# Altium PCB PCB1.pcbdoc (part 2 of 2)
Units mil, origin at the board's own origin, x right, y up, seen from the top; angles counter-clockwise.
Board outline 4437 x 2665.4 mil, 2 copper layers (Top Layer, Bottom Layer), stack 62.206 mil thick; 104 components, 74 nets, 471 pads, 378 vias.
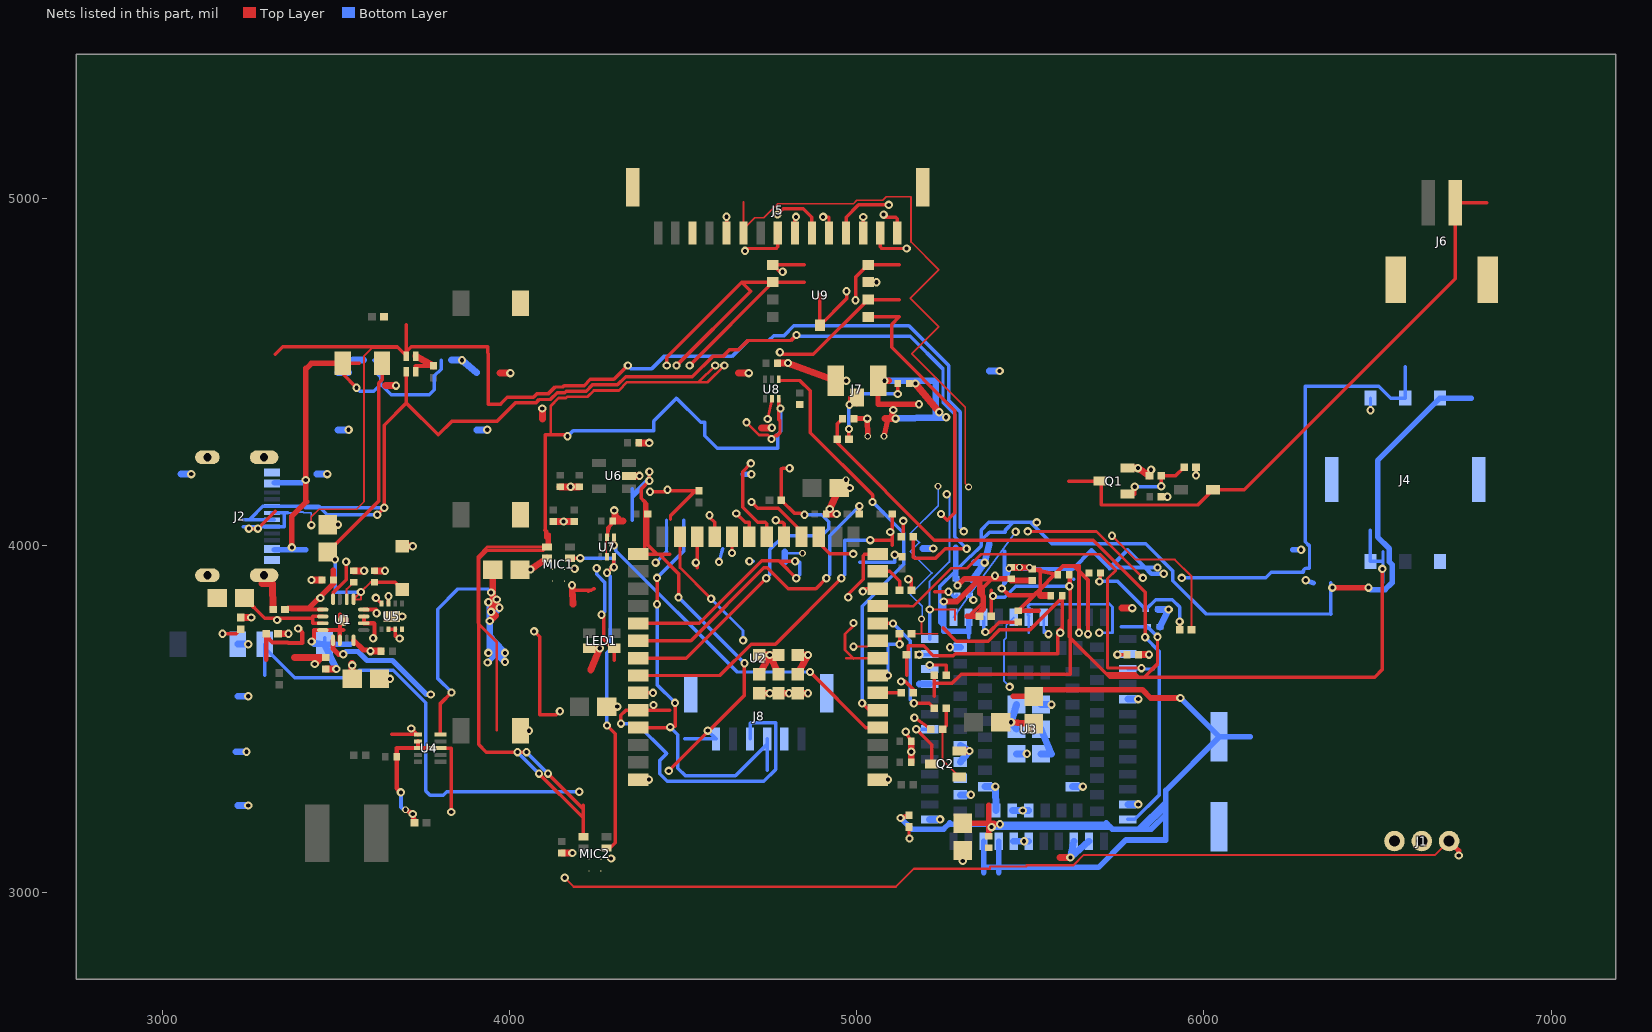
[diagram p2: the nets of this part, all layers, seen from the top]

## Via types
v1: diameter 24, hole 12, Top Layer to Bottom Layer, 334 vias
v2: diameter 24.02, hole 12, Top Layer to Bottom Layer, 30 vias
v3: diameter 19.8, hole 11.8, Top Layer to Bottom Layer, 8 vias
v4: diameter 19.7, hole 11.8, Top Layer to Bottom Layer, 3 vias
v5: diameter 20, hole 12, Top Layer to Bottom Layer, 3 vias

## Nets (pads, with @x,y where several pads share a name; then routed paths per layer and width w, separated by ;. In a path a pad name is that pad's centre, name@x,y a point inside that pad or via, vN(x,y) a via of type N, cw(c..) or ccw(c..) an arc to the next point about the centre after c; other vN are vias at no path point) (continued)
GND: C1.2 C2.2 C3.2 C4.2 C5.2 C6.2 C7.2 C8.2 C9.2 C10.2 C11.2 C12.2 C13.2 C14.2 C15.2 C16.2 C17.2 C18.2 C19.2 C20.2 C21.2 C22.2 C23.2 C24.2 C25.2 C26.2 C27.2 C28.2 C29.2 C30.2 C31.2 C32.2 C33.2 C34.2 C35.2 C36.2 C37.2 C38.2 C39.2 D1.2 D2.2 D3.2 D4.2 D5.2 D6.2 D8.2 J1.2 J2.1 J2.2 J2.3 J2.4 J2.A1B12 J2.B1A12 J4.8 J4.C5 J5.3 J5.16 J5.17 J6.3 J6.4 J7.1 J7.3 J8.2 J8.7 J8.8 LED1.2 MIC1.2 MIC1.3 MIC2.3 Q1.2 Q2.2 R1.2 R2.2 R4.2 R7.2 R8.2 R20.2 R25.2 R27.2 SW1.2 SW2.2 SW3.2 SW4.2 SW5.2 U1.4 U1.6 U1.8 U1.17 U2.1 U2.40 U2.41 U3.1 U3.10 U3.27 U3.34 U3.36 U3.37 U3.40 U3.41 U3.45 U3.46 U3.47 U3.48 U3.70 U3.71 U3.72 U3.73 U3.88 U3.89 U3.90 U3.91 U3.92 U3.93 U3.94 U3.95 U3.100 U4.2 U4.3 U4.8 U5.4 U5.9 U6.2 U7.2 U7.5 U8.2 U9.4 | length 9680.9
  Top Layer w5: U7.2@4278,3966.6 U7.5@4278,4023.4
  Top Layer w8: U7.5@4279.99,4023.45 4280.22,4024.22 4282,4030.86 4289.01,4057.01 v1(4300.71,4100.67) ; v1(4742.73,4363.89) U8.2@4754.99,4421.56
  Top Layer w10: U4.8@3792.11,3415.5 3831.19,3415.5 v1(3831.19,3231.61) ; v1(4179.06,3884.58) 4179.06,3870.89 4179.67,3870.89 4234.33,3870.89 ; 4226.19,3867.09 4234.33,3870.89 ; 4242.5,3874.7 4234.33,3870.89 ; U7.5@4280,4024 4280.22,4024.22 4282,4026 4282,4030.86 4282,4050 4289.01,4057.01 C29.2@4298,4066 ; C29.2@4296.54,4070 4306.03,4075.5 4315.55,4081 ; 4316,4066 4326.5,4070 ; C12.2@4911.54,4090 v1(4921.82,4104.74) ; v1(5140.5,3462.71) C10.2@5156.54,3435 ; C39.2@5150.54,4466 v1(5168.5,4466) ; v1(5165.49,3503.27) R27.2@5212.96,3470 ; C17.2@5505,3931.54 5528.5,3931.5 5528.5,3926.22 5528.5,3874.5 5528.5,3855 ; R25.2@5842.96,4200 v1(5847.66,4217.39) ; C31.2@5876.54,4140 v1(5894.5,4140)
  Top Layer w12: v1(3428.83,3722.9) 3436,3732 3436,3756 3510,3756 3510,3755.5 ; U1.4@3460.95,3755.47 3510,3755.5 ; U1.6@3510,3726 3510,3755.5 ; U1.6@3510.16,3725.95 3510.2,3755.5 ; 3510.2,3800.9 3510.2,3755.5 ; 3520,3755.5 3510.2,3755.5 ; 3674,3300 v1(3686,3288) ; 3674,3300.5 C18.2@3674.04,3390.5 3674,3415.5 U4.3@3735.02,3415.5 ; D2.2@3728.78,4500 3728.8,4517 R7.2@3780,4517.04 ; U4.2@3735.02,3435.18 U4.3@3735.02,3415.5 ; U4.8@3792.11,3415.5 U4.3@3735.02,3415.5 ; v1@5418,3876 5438,3856 5510,3856 ; C16.2@5445,3936.54 C17.2@5505,3931.54 5528.5,3926.22 C14.2@5570.74,3916.74 ; C37.2@5465,3811.54 5525,3811.5 ; C37.2@5466,3812 5510,3856 ; C14.2@5578.46,3915 C14.2@5570.74,3916.74 ; v1(5640,3748) 5640,3926 ; v1(5666,3744) 5666,3900 5640,3926 ; 3510,3755.5 3510.2,3755.5 ; 5510,3856 5528.5,3874.5 C14.2@5570.74,3916.74 ; C14.2@5570.74,3916.74 5594,3940 5626,3940 ; 5626,3940 5640,3940 5640,3926 ; 5626,3940 5640,3926
  Top Layer w15: U1.8@3550,3726 3578,3698 3588,3698 v1(3598.5,3695) ; v3(3699.3,3237.93) v1(3720.09,3225.93) R20.2@3725.46,3200.5 ; SW1.2@4030.9,3465.35 v1(4054.9,3465.4) ; C12.2@4911.54,4090 4928.74,4119.86 4954.8,4165 v3(4968.5,4188.73) ; C12.2@4912,4090 4918,4096 v1(4921.82,4104.74) ; C38.2@4991.54,4365 v1(5029.5,4365) v3(5031.28,4314.03) ; U9.4@5032.38,4758.03 v1(5056.4,4758) ; J7.3@5061.02,4474.1 5061,4406.1 v1(5178.78,4406.1) ; v3(5078.19,4314.14) 5089,4365 ; 5096.5,4365 v1(5104.53,4389.73) ; v3(5468.36,3936.65) 5469.42,3936.5 C17.2@5505,3931.54 ; v3@5475,3936.5 v3(5497,3936.5)
  Top Layer w20: R2.2@3225,3792.04 v1(3255,3792) ; 3285.6,3890 3315.6,3890 R4.2@3317.96,3815 ; R1.2@3332.04,3745 v1(3362,3745) ; v1(3428.5,3900) C7.2@3458.46,3900 ; C5.2@3470,3643.46 v1(3500,3643.5) ; C3.2@3475,4059.37 v1(3505,4059.4) ; C6.2@3550,3926.54 v1(3580,3926.5) ; v1(3598.5,3695) C21.2@3628.46,3695 ; C2.2@3610,3926.54 v1(3640,3926.5) ; C4.2@3624.37,3615 v1(3654.4,3615) ; 3642,4460 v1(3672,4460) ; U5.9@3660,3795 v1(3690,3795) ; D8.2@3690,3997.4 v1(3720,3997.4) ; D1.2@3728.78,4545 R7.2@3780,4517.04 ; 3971.5,4496 v1(4001.5,4496) ; C19.2@4029.37,3930 v1(4059.4,3930) MIC1.2@4107.01,3962.89 ; 4093.5,4364.1 v1(4093.5,4394.1) ; C23.2@4125,4068.46 v1(4155,4068.5) C25.2@4185,4068.46 ; C22.2@4145,4168.46 v1(4175,4168.5) C28.2@4200,4168.46 ; C26.2@4150,3113.46 v1(4180,3113.5) ; v1(4179.06,3884.58) 4179.67,3870.89 4181.5,3830 ; LED1.2@4228.98,3703.34 v1(4259,3703.3) 4233,3640 ; C20.2@4279.37,3535 v1(4309.4,3535) ; C29.2@4296.54,4070 4326.5,4070 ; v1(4300.71,4100.67) C29.2@4306.03,4075.5 ; U6.2@4343.31,4199.99 v1(4373.3,4200) ; U2.40@4370.51,3324.8 v1(4400.5,3324.8) ; C27.2@4371.54,4295 v1(4401.5,4295) ; 4658.5,4495.9 v1(4688.5,4495.9) ; U2.41@4718.94,3573.62 v1(4748.9,3573.6) ; U2.41@4718.94,3628.74 v1(4748.9,3683.9) ; U2.41@4718.94,3683.86 v1(4748.9,3683.9) ; 4725,4338.5 v1(4755,4338.5) ; C30.2@4771.54,4525 v1(4801.5,4525) J7.1@4938.98,4474.1 v1(4969,4474.1) ; U2.41@4774.06,3573.62 v1(4804.1,3573.6) ; U2.41@4774.06,3628.74 v1(4748.9,3683.9) ; U2.41@4774.06,3683.86 v1(4748.9,3683.9) ; U2.41@4829.18,3573.62 v1(4859.2,3573.6) ; U2.41@4829.18,3628.74 v1(4859.2,3683.9) U2.41@4829.18,3683.86 ; C12.2@4911.54,4090 4912,4090 v1(4941.5,4090) ; v1(4921.82,4104.74) 4928.74,4119.86 C11.2@4949.37,4165 4954.8,4165 v1(4979.4,4165) ; U2.1@5059.49,3324.8 v1(5089.5,3324.8) ; J7.3@5061.02,4474.1 5091,4474.1 ; 5081.5,4365 5089,4365 5096.5,4365 v1(5111.5,4365) ; C9.2@5156.54,3375 v1(5156.5,3405) C10.2@5156.54,3435 ; v1(5168.5,4466) v1(5237.42,4383.44) ; Q2.2@5294.37,3407.4 v1(5324.4,3407.4) ; v1(5305,3090.6) C33.2@5305,3120.63 ; C8.2@5414.37,3490 v1(5444.4,3490) C34.2@5510,3485.63 ; C16.2@5445,3936.54 5469.42,3936.5 v3@5475,3936.5 ; 5528.5,3855 C15.2@5558.46,3855 ; 5585,3100.3 v1(5615,3100.3) ; 5763.1,3818.8 v1(5793.1,3818.8) ; Q1.2@5779.37,4222.4 v1(5809.4,4222.4) R25.2@5842.96,4200 ; C36.2@5811.54,3685 v1(5841.5,3685)
  Inner2 w12: v1(5640,3748) 5666,3722 5688,3722 ; v1(5666,3744) 5688,3722 ; v1(5866,3936) 5866,3880 ; v1(5884,3918) 5884,3898 5866,3880 ; 5688,3722 5708,3722 ; 5688,3722 5698,3712 5708,3722 ; 5708,3722 5866,3880
  Bottom Layer w5: U3.95@5278.46,3792.84 5324.22,3855.73 v1(5457.19,4038.74)
  Bottom Layer w6: 4792,3977.11 v3(4842.86,3977.11)
  Bottom Layer w10: SW4.2@3466.02,3715 SW4.2@3466,3733 ; v1(4602.55,3952.06) 4612.9,3990.7 ; 5227.1,4368.7 v1(5237.42,4383.44) ; D5.2@5324,3856 5324.22,3855.73 v1(5335.57,3842.21) ; v1(5417.39,3875.39) 5425,3891.7
  Bottom Layer w12: v1(3686,3288) 3686,3246 3692,3240 v3(3699.3,3237.93) ; 5425,3891.7 5425,3981.7 ; v3@5430,3932 5438.09,3932 5622,3932 5676,3986 5726,3936 ; v1(5866,3936) 5830,3936 ; v1(5884,3918) 5848,3918 5830,3936 ; 5726,3936 5730,3936 ; 5726,3936 5728,3934 5730,3936 ; 5730,3936 5780,3986 5830,3936 ; 5730,3936 5830,3936
  Bottom Layer w15: SW4.2@3466,3714 3436,3714 v1(3428.83,3722.9) SW4.2@3466.02,3715 3541,3715 ; 4671.8,4204.6 v1(4695.8,4204.6) ; 5425,3891.7 5438.09,3932 v3(5438.29,3932.59) ; 6255.9,3987.1 v1(6279.9,3987.1) ; v1(6292.98,3899.12) 6315.8,3891.7
  Bottom Layer w20: 3051.9,4205 v1(3081.9,4205) ; 3211,3405 v1(3241,3405) ; 3216,3250 v1(3246,3250) ; 3216,3565 v1(3246,3565) ; SW5.2@3216.02,3715 v1(3246,3715) ; 3443.6,4205 v1(3473.6,4205) ; SW4.2@3466.02,3715 v1(3500,3643.5) ; 3505.4,4332.7 v1(3535.4,4332.7) ; 3505.4,4497.3 3535.4,4497.3 ; 3548,4533.3 3578,4533.3 ; 3832,4533.3 v1(3862,4533.3) 3904.6,4497.3 ; 3904.6,4332.7 v1(3934.6,4332.7) ; 4792,3951.3 4792,3977.11 4792,3981.3 ; v1(5079,4474.1) 5227.1,4474.1 5227.1,4368.7 ; v1(5111.5,4365) 5227.1,4368.7 ; 5179.6,3599.9 U3.10@5209.57,3599.91 ; 5189.7,3990.7 v1(5219.7,3990.7) ; U3.1@5209.57,3210.16 v1(5239.6,3210.2) ; v1(5257.1,4368.7) 5227.1,4368.7 ; v1(5268.2,3706.2) U3.100@5298.15,3706.22 ; U3.45@5298.15,3281.01 v1(5328.2,3281) ; U3.47@5298.15,3375.51 v1(5324.4,3407.4) U3.48@5298.15,3422.76 ; 5333,3900 v1(5368,3950) ; 5338,3950 v1(5368,3950) ; U3.73@5369.02,3304.64 v1(5399,3304.6) U3.72@5400.51,3235.74 ; 5381.2,4003.1 v1(5368,3950) ; 5381.2,4502.3 v1(5411.2,4502.3) ; U3.71@5447.76,3235.74 v1(5477.8,3235.7) U3.70@5495,3235.74 ; U3.41@5451.69,3147.16 v1(5481.7,3147.2) U3.40@5495,3147.16 ; U3.89@5459.57,3399.12 v1(5489.6,3399.1) ; U3.90@5459.57,3469.99 v1(5444.4,3490) U3.91@5459.57,3540.86 ; U3.94@5530.43,3399.12 5560.4,3399.1 U3.93@5530.43,3469.99 ; U3.92@5530.43,3540.86 v1(5560.4,3540.9) ; U3.88@5620.98,3304.64 v1(5651,3304.6) ; U3.37@5624.92,3147.16 v1(5615,3100.3) U3.36@5668.23,3147.16 ; U3.34@5780.43,3253.45 v1(5810.4,3253.5) ; U3.27@5780.43,3556.61 v1(5810.4,3556.6) ; D3.2@5868,3815 v1(5898,3815) D4.2@5873,3765
  other v1: 4291.7,3097.5 4186.7,3932.5
GPIO0_BOOT: J8.6 R6.1 SW4.1 U2.27 | length 3392.4
  Top Layer w10: U2.27@4370.51,3974.8 4423.2,3974.8 ; U2.27@4388,3978 4388,4126 ; R6.1@4394,4094 4394,4120 4388,4126 ; 4397,4000 R6.1@4397.04,4090 ; 4398,4000 4423.2,3974.8 ; v1(4402,4212) v1(4402,4186) 4378,4162 4378,4136 4388,4126 ; 4424,3974 4423.2,3974.8 ; 4430,3974 4486,3918 v1(4486,3850) ; v1(4458,3350) 4676,3568 v1(4676,3660) ; 4460.5,3974.8 4423.2,3974.8
  Top Layer w15: U2.27@4370.51,3974.8 U2.27@4388,3978
  Inner2 w10: v1(4200,3290) 4260,3350 v1(4458,3350)
  Bottom Layer w10: 3294,3625 SW4.1@3293.98,3715 ; SW4.1@3298,3700 3380,3618 3544,3618 3566,3640 3664,3640 3758,3546 3758,3292 3770,3280 3808,3280 3818,3290 v1(4200,3290) ; 4352,4072 4352,4136 ; 4352,4162.8 4352,4144 ; 4352.9,4072 4352.9,4072.8 4352.9,4136.9 ; v1(4402,4186) 4352.9,4136.9 ; v1(4402,4212) 4402,4194 4352,4144 ; v1(4486,3850) v1(4676,3660) ; 4503.9,3441.9 J8.6@4593.9,3441.93 ; v1(4570,3466) J8.6@4594,3442 ; 4352,4136 4352.9,4136.9 ; 4352,4136 4352,4144
I2C_SCL: J5.13 U2.17 U5.7 | length 2688.9
  Top Layer w9.88: U5.7@3650.16,3831.91 v2(3650.16,3853.23)
  Top Layer w10: U2.17@4890,4025.2 4890,4007.07 4921.75,3975.32 v2(4989.2,3975.32) ; J5.13@5017.97,4900.05 v2(5017.97,4945.71)
  Inner1 w9.88: v2(3650.16,3853.23) 3786.05,3989.12 4213.43,3989.12 4240.12,3962.43 4295.42,3962.43 4335.48,4002.49 4962.03,4002.49 v2(4989.2,3975.32)
  Inner1 w10: v2(4989.2,3975.32) 5040.83,3975.32 5071.8,4006.29 5071.8,4170.93 5054.78,4187.95 5054.78,4448.82 5020.34,4483.26 5020.34,4943.34 v2(5017.97,4945.71)
I2C_SDA: J5.12 U2.12 U5.8 | length 3002.8
  Top Layer w9.88: v2(3613.83,3848.55) U5.8@3630.47,3831.91 ; J5.12@4968.76,4900.07 4968.77,4944.97 5004.56,4980.77 v2(5091.58,4980.77)
  Top Layer w10: v2(5017.11,3867.24) 5018.45,3868.58 5018.45,3870.23 5023.03,3874.81 U2.12@5059.49,3874.8
  Inner1 w9.88: v2(3613.83,3848.55) 3644.29,3818.09 3848.42,3818.09 3908.93,3757.58 3950.59,3757.58 3969.47,3776.46 4078.2,3776.46 4083.65,3771.01 4816.79,3771.01 4858.95,3813.17 4973.06,3813.17 5017.11,3857.23 v2(5017.11,3867.24) 5042.72,3867.24 5159.99,3984.51 5159.99,4192.16 5205.21,4237.38 5205.21,4867.14 v2(5091.58,4980.77)
LCD_BL_PWM: J5.11 U2.21 | length 1243.8
  Top Layer w6: J5.11@4919.6,4900 J5.11@4919.55,4900.07
  Top Layer w10: v2(4652.35,4091.62) 4677.75,4066.22 4690,4066.22 U2.21@4690,4025.2 ; v2(4902.64,4946.21) 4903.82,4945.03 4919.56,4945.03 J5.11@4919.55,4900.07
  Inner1 w10: v2(4652.35,4091.62) 4643.45,4100.52 4643.45,4857.79 4763.88,4978.22 4870.63,4978.22 v2(4902.64,4946.21)
LCD_CS: J5.8 U2.18 | length 1081.3
  Top Layer w10: v2(4677.56,4848.19) 4684.48,4855.11 4767.34,4855.11 4771.92,4859.69 J5.8@4771.91,4900.07 ; v2(4696.31,4124.56) 4713.81,4107.06 4773.63,4107.06 4840,4040.69 U2.18@4840,4025.2
  Inner1 w10: v2(4677.56,4848.19) 4657.64,4828.27 4657.64,4163.23 v2(4696.31,4124.56)
LCD_DC: J5.9 U2.19 | length 1138.6
  Top Layer w10: v2(4766.17,4072.05) 4772,4066.22 4785.42,4066.22 4790,4061.64 U2.19@4790,4025.2 ; J5.9@4821.12,4900.07 4821.13,4942.98 v2(4824.46,4946.3)
  Inner1 w10: v2(4766.17,4072.05) 4833.37,4139.25 4908.46,4139.25 4925.94,4156.73 4925.94,4844.82 v2(4824.46,4946.3)
LCD_MOSI: J5.5 R22.2 | length 2142.7
  Top Layer w10: J5.5@4624.3,4900 J5.5@4624.27,4900.07 ; J5.5@4624.27,4900.07 v2(4624.28,4946.37) ; v2(5127.22,3607.57) 5139.42,3607.57 5162.04,3584.95 R22.2@5162.04,3575
  Inner1 w10: v2(4624.28,4946.37) 4685.34,5007.42 5097.79,5007.42 5285.71,4819.51 5285.71,4067.59 5255.77,4037.65 5255.77,3893.91 5146.15,3784.29 5146.15,3626.5 v2(5127.22,3607.57)
LCD_MOSI_MCU: R22.1 U2.6 | length 68.6
  Top Layer w10: U2.6@5059.49,3574.8 5059.7,3575 R22.1@5127.96,3575
LCD_RST: J5.10 U2.20 | length 1276.1
  Top Layer w10: v2(4694.37,4235.91) 4670.54,4212.08 4670.54,4109.88 4714.2,4066.22 4735.42,4066.22 4740,4061.64 U2.20@4740,4025.2 ; v2(4771.25,4952.84) 4788.24,4969.82 4845.54,4969.82 4870.34,4945.03 J5.10@4870.33,4900.07
  Inner1 w10: v2(4694.37,4235.91) 4719.39,4235.91 4879.34,4395.86 4879.34,4844.75 v2(4771.25,4952.84)
LCD_SCLK: J5.6 R23.2 | length 2364.6
  Top Layer w5: J5.6@4673.5,4900 J5.6@4673.48,4900.07 4673.5,4990.1 ; J5.6@4674,4912 4706,4944 4732,4944 4772,4984 4990,4984 5000,4994 5074,4994 5084,5004 5156,5004 5156,4874 5236,4794 5154,4712 5236,4630 5158,4552 5312,4398 5312,4178 v5(5322,4168) ; R23.2@5157.04,3745 5232,3745 ; 5186,3746 v5(5186,3788)
  Inner2 w5: v5(5234,4170) 5268,4170 5280,4158 5312,4158 v5(5322,4168)
  Bottom Layer w5: v5(5186,3788) 5188,3790 5188,3824 5154,3858 5216,3920 5154,3982 5180,4008 5154,4034 5234,4114 v5(5234,4170)
LCD_SCLK_MCU: R23.1 U2.7 | length 183.7
  Top Layer w10: U2.7@5059.49,3624.8 v1(5089.5,3624.8) ; v1(5123,3715) R23.1@5122.96,3745
  Bottom Layer w10: v1(5089.5,3624.8) 5089.5,3715 v1(5123,3715)
LED_DATA: LED1.3 U2.24 | length 703.7
  Top Layer w10: v1(4264,3800) 4270,3794 4270,3728 4294,3704 LED1.3@4302,3704 ; 4301,3668.3 LED1.3@4301.02,3703.34 ; 4540,3935.2 U2.24@4540,4025.2
  Inner2 w10: v1(4250,3934) 4292,3976 4510,3976 v1(4536,3950)
  Bottom Layer w10: v1(4250,3934) 4250,3916 4274,3892 4274,3810 v1(4264,3800)
LTE_ANT: C38.1 R29.1 U3.35 | length 1862.4
  Top Layer w10: R29.1@4942.96,4305 4942.96,4295 5222.96,4015 5680.43,4015 5830.43,3865 v1(5830.43,3735) ; R29.1@4942.96,4305 4943,4349.5 C38.1@4958.46,4365
  Bottom Layer w10: U3.35@5780.43,3210.16 5800.43,3210.15 5870.43,3280.15 5870.43,3695 v1(5830.43,3735)
LTE_ANT_CONN: C39.1 J7.2 R29.2 | length 346.8
  Top Layer w10: R29.2@4977.04,4305 v1(4977,4335) ; v1(4978.79,4404.69) 4978.79,4425.9 J7.2@5000,4425.9 J7.2@5000,4404.69 ; v1(5117.5,4436) C39.1@5117.46,4466
  Bottom Layer w10: v1(4977,4335) 4977,4404.69 v1(4978.79,4404.69) 5010.09,4436 v1(5117.5,4436)
MIC_CLK_1V8: MIC1.4 MIC2.4 U7.3 | length 1064.8
  Top Layer w6: v1(4299.7,3936.6) U7.3@4299.69,3966.55
  Top Layer w9.92: MIC2.4@4277.99,3127.89 4288.64,3127.89 4303.32,3142.57 4303.32,3457.24 v1(4279.69,3480.87) ; v1(4279.69,3920.87) 4299.69,3940.87 U7.3@4299.69,3966.55
  Top Layer w10: MIC1.4@4172.99,3962.89 v1(4203,3962.9)
  Bottom Layer w9.92: v1(4279.69,3480.87) 4279.69,3690.87 4289.69,3700.87 4289.69,3910.87 v1(4279.69,3920.87)
  Bottom Layer w10: v1(4203,3962.9) 4299.7,3962.9 v1(4299.7,3936.6)
MIC_DATA_1V8: MIC1.1 MIC2.1 U8.3 | length 4968.9
  Top Layer w8: 3962,3468 3962,3722 3910,3774 3908,3776 3908,3968 3936,3996 4106,3996 4107,3996 4114,3996 4114,4032 4112,4032 4107,4037 4105,4039 ; 4102,4044 4102,4042 4102,4022 4106,4018 ; 4118,4318 4118,4402 4140,4424 4162,4424 4166,4428 4224,4428 4242,4446 4314,4446 4338,4470 4544,4470 ; v1(4592,4518) 4544,4470 ; v1(4618,4518) 4570,4470 4544,4470 ; v1(4682,4354) 4718,4318 4744,4318 4748,4314 v1@4762,4314 ; v1(4754,4306) v1@4762,4314 ; 4778,4360 4778,4326 ; v1@4762,4314 4766,4318 4770,4318 4778,4326 ; v1@4762,4314 4770,4314 4778,4322 4778,4326
  Top Layer w10: v1(4048,3404) 3932,3404 3910,3426 3910,3774 3910,3962 3934,3986 4096,3986 MIC1.1@4106,3996 ; v1(4084,3342) 4208,3218 ; 4101,4043 4102,4042 4105,4039 ; 4102,4044 4102,4318 4118,4318 4162,4318 v1(4166,4314) ; MIC1.1@4107.01,3995.26 4107,3996 4107,4037 4107,4040.3 ; v1(4110,3342) 4212,3240 ; MIC2.1@4212.01,3160.26 4212,3240 ; 4212,3250.3 4212,3240 ; 4774.7,4361.6 U8.3@4774.69,4421.56 ; v1@4778,4394 v1(4780,4394)
  Inner2 w8: v1(4592,4518) 4682,4428 v1(4682,4354) ; v1(4618,4518) 4704,4432 4704,4356 v1(4754,4306)
  Bottom Layer w10: v1(4022,3404) v1(4084,3342) ; v1(4048,3404) v1(4110,3342) ; v1(4166,4314) 4182,4330 4414,4330 4414,4358 4480,4424 4550,4354 4562,4354 4562,4316 4598,4280 4772,4280 4772,4320 4780,4328 v1(4780,4394)
MIC_PDM_CLK: U2.4 U7.4 | length 1006.6
  Top Layer w9.92: v1(4299.69,4000.12) U7.4@4299.69,4023.45 ; v1(4865,3634.8) 5025,3474.8 U2.4@5059.49,3474.8
  Bottom Layer w9.92: v1(4299.69,4000.12) 4305.01,3994.8 4305.01,3984.8 4655,3634.8 v1(4865,3634.8)
MIC_PDM_DATA: U2.5 U8.4 | length 1218.6
  Top Layer w9.92: U8.4@4774.69,4478.44 4778.33,4474.8 4835,4474.8 4865,4444.8 4865,4324.8 5045,4144.8 v1(5045,4124.8) ; v1(5015,3544.8) 5035,3524.8 U2.5@5059.49,3524.8
  Bottom Layer w9.92: v1(5015,3544.8) 5015,3824.8 5135,3944.8 5135,4034.8 v1(5045,4124.8)
MICROSD_N5: R12.1 U9.7 | length 3420.9
  Top Layer w10: v1(4404,4154) v1@4452,4154 ; v1(4452,4518) 4452,4542 4668,4758 ; v1@4455,4157 R12.1@4545,4157.04 ; 4462.8,4074.84 4462.8,4084.84 4532.8,4154.84 4542.8,4154.84 R12.1@4545,4157.04 ; v1(4480,4518) 4694,4732 4668,4758 ; v1(4518,4518) U9.7@4758,4758 ; R12.1@4545,4157.04 R12.1@4545,4157.04 ; 4667.6,4758 4668,4758 ; 4847.6,4758 U9.7@4758,4758 ; 4668,4758 U9.7@4757.6,4758.03 U9.7@4758,4758
  Inner2 w10: v1(4404,4154) 4298,4154 4292,4160 ; v1(4452,4518) 4452,4474 ; v1(4454,4160) 4292,4160 ; v1(4480,4518) 4480,4502 4452,4474 ; v1(4518,4518) 4320,4320 4298,4320 ; v1(4690,3954) 4714,3930 4738,3954 4738,3984 4704,4018 4704,4060 4550,4060 4550,4126 4296,4126 4294,4124 4272,4124 4272,4160 ; 4272,4160 4260,4160 4260,4282 4272,4294 ; 4272,4160 4292,4160 ; 4272,4160 4272,4294 ; 4272,4294 4298,4320 ; 4298,4320 4452,4474
  Bottom Layer w10: v1(4690,3954) 4702,3954
MICROSD_N6: R13.1 U9.1 | length 1452.3
  Top Layer w10: U9.1@4893.15,4633.62 4893.2,4723.6 ; U9.1@4894,4634 4970,4710 v1(4970,4732) ; v1(5108.79,3972.51) 5130,3972.51 R13.1@5130,3967.04
  Inner2 w10: v1(4970,4732) 5066,4732 5142,4656 5142,4224 5268,4098 5268,4004 5230,3966 5118,3966 v1(5108.79,3972.51)
  Bottom Layer w10: 5008.6,3951.3 5108.79,3951.3 v1(5108.79,3972.51)
MODEM_DTR: U2.25 U3.19 | length 1368.4
  Top Layer w8: 4490,3935.2 4490,3936 ; U2.25@4490,4025.2 4490,3936 ; v1(4580,3846) 4490,3936
  Inner2 w8: v1(4672,3726) 4682,3736 5068,3736 5112,3692 5154,3692 5198,3736 5344,3736 5356,3724 5532,3724 v1(5552,3744)
  Bottom Layer w8: v1(4580,3846) 4672,3754 v1(4672,3726) ; 5538.3,3747.8 U3.19@5538.31,3792.84 ; 5542,3754 v1(5552,3744)
MODEM_PWRKEY_DRV: R26.1 U2.10 | length 364.5
  Top Layer w10: U2.10@5059.49,3774.8 v1(5104.02,3774.81) ; v1(5164.02,3544.81) 5208.15,3544.81 R26.1@5222.96,3530
  Bottom Layer w10: v1(5104.02,3774.81) 5154.02,3724.81 5154.02,3554.81 v1(5164.02,3544.81)
MODEM_PWRKEY_N: Q2.3 U3.7 | length 157.1
  Top Layer w10: v1(5170.94,3470) 5215.63,3425.31 Q2.3@5215.63,3370
  Bottom Layer w10: v1(5170.94,3470) U3.7@5209.57,3469.99
MODEM_RESET_N: C37.1 U3.15 | length 151.6
  Top Layer w10: v1(5370,3750) 5382,3750 5410,3778 ; 5410,3778.5 C37.1@5465,3778.46
  Bottom Layer w10: v1@5365.1,3747.8 U3.15@5365.08,3792.84
MODEM_RXD: U2.8 U3.18 | length 1897.7
  Top Layer w8: 4969.5,3674.8 4989.2,3674.8 ; 4990,3674 4989.2,3674.8 ; v1(4990,3776) 4990,3768 4966,3744 4966,3698 4989.2,3674.8 ; U2.8@5060,3674.8 U2.8@5059.49,3674.8 4989.2,3674.8 ; v1(5492,4040) 5690,4040 v1(5824,3906)
  Inner2 w8: v1(4990,3776) 5072,3776 5094,3798 5124,3798 5156,3766 5218,3766 v1(5492,4040) ; v1(5698,3748) 5698,3780 v1(5824,3906)
  Bottom Layer w8: 5495,3747.8 U3.18@5495,3792.84 ; U3.18@5496,3796 5492,3800 5498,3806 5492,3812 5498,3818 5492,3824 5498,3830 5720,3830 5724,3834 5736,3822 5736,3748 v1(5698,3748)
MODEM_STATUS: U2.11 U3.25 | length 1232.1
  Top Layer w8: U2.11@5059.49,3824.8 5149.5,3824.8 ; 5150,3824 5162,3824 5272,3934 5318,3934 5358,3974 5700,3974 5746,3928 5722,3904 5722,3646 v1(5820,3646)
  Bottom Layer w8: U3.25@5780.43,3643.22 5855.4,3643.2
MODEM_TXD: U2.9 U3.17 | length 790.2
  Top Layer w5: v1(4990,3708) 5030,3708 U2.9@5059.49,3724.8
  Inner2 w5: v1(4990,3708) 5038,3708 5114,3632 5400,3632 v1(5440,3592)
  Bottom Layer w5: v1(5440,3592) 5424,3608 5424,3728 5430,3734 5430,3770 U3.17@5452,3792
MODEM_VDD_EXT: C36.1 U3.24 | length 59.6
  Top Layer w9.84: v1(5750.4,3685) C36.1@5778.46,3685
  Bottom Layer w9.84: v1(5750.4,3685) 5780.4,3685 U3.24@5780.43,3686.53
MOTOR_GATE: Q1.1 R24.2 R25.1 | length 226.4
  Top Layer w10: Q1.1@5779.37,4147.6 5800.61,4147.6 v1(5800.61,4168.81) ; v1(5877,4170) R25.1@5877.04,4200 5918,4200 R24.2@5942.96,4225
  Bottom Layer w10: v1(5800.61,4168.81) 5877,4168.81 v1(5877,4170)
MOTOR_N: D7.2 J6.2 Q1.3 | length 1750.1
  Top Layer w10: 5610.6,4185 Q1.3@5700.63,4185 ; Q1.3@5704,4182 5704,4116 5982,4116 D7.2@6026,4160 ; D7.2@6026.16,4160 6116,4160 ; 6116.2,4160 6116,4160 ; J6.2@6724,4982 6724,4768 6116,4160 ; J6.2@6724.41,4986.95 6814.4,4986.9
MOTOR_PWM: R24.1 U2.35 | length 1960.6
  Top Layer w10: U2.35@4370.51,3574.8 v1(4412.59,3574.8) ; v1(5977.04,4201.37) R24.1@5977.04,4225
  Inner2 w10: v1(4412.59,3574.8) 4588.16,3750.37 5323.77,3750.37 5414.67,3841.27 5723.96,3841.27 5986.95,4104.26 5986.95,4191.46 v1(5977.04,4201.37)
POWER_CHARGE_N4: C7.1 J1.3 R4.1 U1.1 | length 4624.5
  Top Layer w6: v1(4158,3042) 4184,3016 5112,3016 5164,3068 5384,3068 5384,3074 5488,3074 5488,3078 5624,3078 5654,3108 6666,3108 J1.3@6706,3148
  Top Layer w10: 3492,3886 C7.1@3492,3890 ; v1(4070,3752) 4086,3736 4086,3512 4134,3512 v1(4144,3522) ; v1(6734,3106) 6734,3120
  Top Layer w12: 3370.9,3814.5 U1.1@3460.95,3814.53
  Top Layer w15: J1.3@6706.28,3147.69 6734,3120
  Top Layer w16: R4.1@3352.04,3815 3362,3818 3420,3818 3492,3890 C7.1@3492,3900 ; C7.1@3491.54,3900 3491.5,3928
  Inner2 w6: v1(4158,3042) 4158,3124
  Inner2 w10: v1(3454,3848) 3496,3848 3498,3850 3520,3850 3560,3890 4064,3890 4064,3758 v1(4070,3752) ; v1(4144,3522) 4152,3514 4152,3204 4118,3170 4160,3128 4180,3148 ; 6734,3072 v1(6734,3106)
POWER_CHARGE_N5: R1.1 U1.12 | length 518.5
  Top Layer w12: 3298,3670 R1.1@3298,3738 ; R1.1@3298,3746 R1.1@3297.96,3745 R1.1@3298,3738 ; v1(3390,3760) 3402,3748 3402,3718 3362,3718 3360,3720 3316,3720 R1.1@3298,3738 ; U1.12@3579.05,3814.53 v1@3614.1,3814.5 ; v1(3616,3804) v1@3616,3808
  Inner2 w12: v1(3390,3760) 3396,3766 3574,3766 3612,3804 v1(3616,3804)
POWER_CHARGE_N6: R2.1 U1.16 | length 624.4
  Top Layer w10: v2(3171.91,3745.07) 3212.11,3745.07 R2.1@3225,3757.96 ; U1.16@3490.47,3844.05 3490.48,3862.7 3528.15,3900.37 v2(3528.15,3952.37)
  Inner1 w10: v2(3171.91,3745.07) 3247.54,3820.7 3393.01,3820.7 3524.68,3952.37 v2(3528.15,3952.37)
POWER_CHARGE_N7: C6.1 U1.14 | length 57.8
  Top Layer w6: U1.14@3529.84,3844.05 3529.8,3873.3 C6.1@3550,3893.46
PWRKEY_BASE: Q2.1 R26.2 R27.1 | length 221.2
  Top Layer w6: R27.1@5247.04,3470 5247,3380 Q2.1@5294.37,3332.6
  Top Layer w10: R27.1@5247.04,3470 5257,3480 R26.2@5257.04,3530
SD_CS: R11.1 U2.34 U9.2 | length 2028.9
  Top Layer w10: U2.34@4370.51,3624.8 4605.23,3624.8 4695.28,3714.84 4765.28,3714.84 v1(4955.28,3904.84) ; U9.2@5032.38,4658.03 5122,4658 ; v1(5038.36,4014.94) 5102,4014.94 ; v1(5096,4038) v1@5098,4038 ; 5102,4000 5102,4014.94 ; R11.1@5102.04,4090 5102,4014.94 ; 5122.4,4658 5122,4658 ; v1(5242,4090) 5260,4072 5282,4094 5282,4388 5100,4570 5100,4636 5122,4658
  Inner2 w10: v1(5096,4038) 5096,4068 5124,4096 5142,4096 5148,4090 v1(5242,4090)
  Bottom Layer w10: v1(4955.28,3904.84) 4965.28,3914.84 4965.3,4014.94 v1(5038.36,4014.94)
SD_MISO: R14.1 U2.33 U9.6 | length 1765.9
  Top Layer w10: U2.33@4370.51,3674.8 4508.69,3674.8 v1(4738.74,3904.84) ; U9.6@4757.6,4808.03 U9.6@4758,4808 ; 4782,4220 R14.1@4782.04,4130 4820,4092 4838,4092 v1(4848.74,4087.84) ; 4786,4222 v1(4806,4222) ; v1(4786,4788) 4778,4788 U9.6@4758,4808 ; 4847.6,4808 U9.6@4758,4808
  Inner2 w10: v1(4786,4788) 4786,4582 4826,4542 4826,4222 v1(4806,4222)
  Bottom Layer w10: v1(4738.74,3904.84) 4748.74,3914.84 4748.74,3987.84 4788.74,4027.84 4898.74,4027.84 4918.74,4047.84 4918.74,4067.84 4898.74,4087.84 v1(4848.74,4087.84)
SD_MOSI: R15.1 U2.32 U9.5 | length 1739.8
  Top Layer w10: U2.32@4370.51,3724.8 4521.92,3724.8 4731.97,3934.84 4741.97,3934.84 4801.96,3874.84 4881.96,3874.84 v1(4911.96,3904.84) ; v1(4996,4706) 4996,4772 U9.5@5032,4808 ; R15.1@5007.04,4090 v1(5007.04,4112.91) ; U9.5@5032.38,4808.03 5122.4,4808
  Inner2 w10: v1(4996,4706) 4996,4422 5004,4414 5004,4124 v1(5007.04,4112.91)
  Bottom Layer w10: v1(4911.96,3904.84) 4921.96,3914.84 4921.96,4027.84 v1(5007.04,4112.91)
SD_SCLK: U2.31 U9.3 | length 1744.5
  Top Layer w10: U2.31@4370.51,3774.8 4545.32,3774.81 4725.35,3954.84 4775.35,3954.84 v1(4825.35,3904.84) ; v1(4778,4556) 4784,4550 4874,4550 U9.3@5032,4708 ; 4780,3954 v1(4822,3954) ; U9.3@5032.38,4708.03 5122.4,4708
  Inner2 w10: v1(4778,4556) 4778,4530 4754,4506 4780,4480 4720,4420 4780,4360 4780,4118 4790,4108 4790,3986 v1(4822,3954)
  Bottom Layer w10: v1(4825.35,3904.84) 4835.35,3914.84 4835.35,3951.34
SIM_CLK: R16.1 U3.13 | length 1502.9
  Top Layer w5.98: v2(5734.91,4027.59) 5803.68,3958.82 5915.89,3958.82 5963.89,3910.82 R16.1@5963.89,3757.09
  Top Layer w6: v1(5209.6,3815) 5282,3815 5282,3785
  Inner2 w5.98: v2(5258.72,4147.06) 5615.44,4147.06 v2(5734.91,4027.59)
  Bottom Layer w5.98: v1(5209.6,3815) 5209.6,3895.79 5266.13,3952.32 5266.13,4139.65 v2(5258.72,4147.06)
  Bottom Layer w10: U3.13@5209.57,3729.84 v1(5209.6,3815)
SIM_DATA: R17.1 U3.11 | length 89.2
  Top Layer w10: v1(5209.6,3655) 5257,3655 R17.1@5257.04,3625
  Bottom Layer w6: U3.11@5209.57,3643.22 v1(5209.6,3655)
SIM_N2: C15.1 D5.1 J4.C2 R19.2 | length 3434.4
  Top Layer w10: 5143,3625 R19.2@5142.96,3685 R19.2@5148,3685 ; R19.2@5148,3684 R19.2@5148,3685 ; 5224,3866 v1(5264,3866) ; 5248,3762 5286,3724 5378,3724 5410,3756 5498,3756 C15.1@5591.5,3849.5 ; v1(5586,3748) 5592,3754 5592,3766 ; C15.1@5591.54,3855 C15.1@5591.5,3849.5 ; C15.1@5591.54,3855 5592,3854.54 5592,3854 C15.1@5592,3850 ; R19.2@5148,3685 5148,3710 5192,3710 5220,3682 5278,3682 5284,3688 5578,3688 5578,3752 5591.5,3765.5 ; 5591.5,3765.5 5592,3766 ; 5591.5,3765.5 C15.1@5591.5,3849.5 ; C15.1@5591.5,3849.5 C15.1@5592,3850 ; 5592,3766 C15.1@5592,3850
  Inner1 w10: v1(5264,3866) 5327.26,3802.74 5531.26,3802.74 v1(5586,3748)
  Inner2 w10: v1(5586,3748) 5640,3694 5724,3694 v1(5936,3906)
  Bottom Layer w10: v1(5264,3866) 5280,3850 D5.1@5288,3856 ; v1(5936,3906) 6178,3906 6194,3922 6286,3922 6286,3926 6288,3926 6288,3930 6290,3932 ; 6294,3934 6304,3934 6304,3998 6292,4010 6292,4458 6504,4458 6538,4424 J4.C2@6579.72,4424 ; J4.C2@6579.72,4424.22 J4.C2@6579.72,4424 ; J4.C2@6579.72,4424.22 6579.72,4514.2 ; J4.C2@6580,4424 J4.C2@6579.72,4424
SIM_N4: C13.1 D3.1 J4.C3 R16.2 | length 1247.9
  Top Layer w10: v2(5698.46,3895.76) 5701.54,3898.84 C13.1@5701.54,3920 ; R16.2@5929.81,3757.09 v2(5929.81,3780.11)
  Inner1 w10: v2(5929.81,3780.11) 6479.72,4330.02 v2(6479.72,4388.96)
  Bottom Layer w10: v2(5698.46,3895.76) 5751.24,3895.76 D3.1@5832,3815 5860.45,3843.45 5908.51,3843.45 5929.81,3822.15 v2(5929.81,3780.11) ; v2(6479.72,4388.96) J4.C3@6479.72,4424.22
SIM_N6: C14.1 D4.1 J4.C7 R17.2 R18.1 | length 2944.2
  Top Layer w10: 5223,3565 R17.2@5222.96,3625 ; 5228,3602 5274,3602 5300,3628 5614,3628 5614,3734 ; R18.1@5387.04,3795 5387,3870 ; v1@5611.5,3880 C14.1@5611.54,3915 ; v1@5612,3880 v1@5614,3878 ; C14.1@5612,3914 5614,3912 v1@5614,3878 ; v1(5866,3736) 5866,3658 5828,3620 ; v1(6514,3932) 6514,3642 6492,3620 5828,3620 ; 5614,3734 5612,3736 5612,3784 5614,3784 ; 5614,3734 5614,3784 ; 5614,3734 5718,3630 ; 5614,3784 v1@5614,3878 ; 5718,3630 5802,3630 5812,3620 ; 5718,3630 5728,3620 5812,3620 ; 5812,3620 5828,3620
  Bottom Layer w10: v1(5392,3854) 5396,3850 5426,3850 5458,3882 v1(5612,3882) ; 5762,3765 D4.1@5837,3765 ; D4.1@5840,3762 v1(5866,3736) ; J4.C7@6479.72,3953.75 6479.7,4043.8 ; J4.C7@6480,3954 6512,3954 ; 6515.8,3891.7 6515.8,3981.7
SIM_RST: R19.1 U3.12 | length 34.1
  Top Layer w10: R19.1@5177.04,3685 v1(5179.6,3685)
  Bottom Layer w10: v1(5179.6,3685) 5209.6,3685 U3.12@5209.57,3686.53
SIM_VDD: C16.1 C17.1 D6.1 J4.C1 R18.2 U3.14 | length 3781.4
  Top Layer w10: 5322,3794 5323,3795 5364,3836 5366,3838 ; 5364,3852 5364,3880 ; 5366,3880 5389.5,3903.5 v1(5398,3912)
  Top Layer w15: 5354,3904 5355,3903.5
  Top Layer w16: v1(5250,3838) 5288,3838 5354,3904 ; v1(5290,3884) 5310,3904 5354,3904 ; 5318,3795 5323,3795 R18.2@5352.96,3795 ; R18.2@5350,3802 5364,3816 5364,3836 5364,3852 5354,3862 5354,3904 ; 5355,3903.5 5389.5,3903.5 C16.1@5445,3903.46 ; C16.1@5445,3898.5 C17.1@5505,3898.46 ; v1(6370,3878) v1(6474,3878)
  Inner2 w10: v1(5398,3912) 5398,3924 5488,4014 5500,4014 5518,4032 v1(5518,4066)
  Bottom Layer w10: 5262,3754 5250,3766 5238,3778 5238,3880 5285,3927 5326,3968 5328,3968 5358,3998 5358,4014 ; 5314,3752 5318,3752 ; 5321.8,3732.8 5321.8,3747.8 ; v1(5518,4066) 5500,4066 ; 6365.8,3801.7 6365.8,3802 ; 6365.8,3891.7 6365.8,3802 ; 6366,3802 6365.8,3802 ; 5358,4014 5382,4038 5428,4038 5428,4044 5450,4066 ; 5358,4014 5358,4044 5380,4066 5450,4066 ; 5450,4066 5500,4066 ; 5500,4066 5562,4004 5832,4004 5910,3926 5910,3898 6006,3802 6365.8,3802
  Bottom Layer w16: v1(5250,3838) 5250,3766 5250,3752 5314,3752 ; D6.1@5285,3904 5285,3927 5285,3994 ; v1(5290,3884) D6.1@5290,3898 ; 5321.8,3747.8 U3.14@5321.77,3792.84 ; v1(6474,3878) 6480,3872 6522,3872 6542,3892 6542,3944 6534,3952 6534,3990 6500,4024 6500,4244 J4.C1@6680,4424 ; J4.C1@6679.72,4424.22 6769.7,4424.2
TP_INT: J5.14 U2.22 | length 1607.7
  Top Layer w10: v2(4640,3977.78) U2.22@4640,4025.2 ; J5.14@5067.22,4900.05 5067.22,4859.67 5071.8,4855.09 v2(5143.07,4855.09)
  Inner1 w10: v2(4640,3977.78) 4640,3966.14 4727.15,3878.99 4978.24,3878.99 5120.42,4021.17 5120.42,4048.51 5106.14,4062.79 5106.14,4089.33 5143.07,4126.26 v2(5143.07,4855.09)
TP_RST: J5.15 U2.23 | length 1491.5
  Top Layer w10: v2(4575,4086.63) 4575,4081.22 4590,4066.22 U2.23@4590,4025.2 ; v2(5077,4952.65) 5084.65,4945.01 5111.85,4945.01 5116.43,4940.43 J5.15@5116.43,4900.05
  Inner1 w10: v2(4575,4086.63) 4548.63,4113 4548.63,4517.08 4621.57,4590.02 4621.57,4855.98 4758.14,4992.54 5037.11,4992.54 v2(5077,4952.65)
UART0_RXD: J8.4 U2.36 | length 1701.5
  Top Layer w10: v1(4320,3486) 4320,3510 4334,3524 U2.36@4366,3524 ; U2.36@4370.51,3524.8 4460.5,3524.8 ; 4414,3528 v1(4414,3540)
  Inner2 w10: v1(4414,3540) 4412,3540 4388,3564 4388,3760 4330,3818 4328,3818 4294,3852 4294,3874 4370,3950 v1(4420,3950)
  Bottom Layer w10: v1(4320,3486) 4366,3486 4452,3400 4432,3380 4432,3342 4454,3320 4732,3320 4766,3354 4766,3488 4694,3488 4692.3,3486.3 ; v1(4420,3950) 4452,3982 ; 4451.3,3982.8 4451.3,4072.8 ; 4692,3486 4692.3,3486.3 ; J8.4@4692.32,3441.93 4692.3,3486.3 ; 4692.3,3486.9 4692.3,3486.3
UART0_TXD: J8.3 U2.37 | length 1271.5
  Top Layer w10: U2.37@4370.51,3474.8 v1@4460.5,3474.8 ; v1(4424,3830) v1(4424,3906) ; v1@4464,3478 4476,3478 v1(4476,3546)
  Bottom Layer w10: v1(4424,3830) 4424,3598 v1(4476,3546) ; v1(4424,3906) 4500,3982 ; v1(4462,3476) 4484,3454 4484,3358 4506,3336 4650,3336 J8.3@4741.5,3427.5 ; 4500.5,3982.8 4500.5,4072.8 ; 4741.5,3351.9 J8.3@4741.5,3427.5 ; J8.3@4741.5,3442 J8.3@4741.53,3441.93 J8.3@4741.5,3427.5 ; J8.3@4742,3428 J8.3@4741.5,3427.5
USB_DM: D1.1 J2.A7 J2.B7 R9.2 | length 4388.4
  Top Layer w5: v1(3428,4058) 3428,4082 3450,4104 3558,4104 3580,4126 3580,4546 3602,4568 3680,4568
  Top Layer w10: v1(3248,4048) v1@3270,4048 ; v1(3274,4048) 3324,4098 ; 3324,4550 3346,4572 3676,4572 3680,4568 D1.1@3701.2,4546.8 ; D1.1@3701.22,4545 D1.1@3701.2,4546.8 ; 3701.2,4635 D1.1@3701.2,4546.8 ; D1.1@3702,4546 D1.1@3701.2,4546.8 ; D1.1@3702,4558 3716,4572 3936,4572 3936,4554 3938,4552 3938,4406 3974,4406 3974,4408 3992,4426 4068,4426 4078,4436 4110,4436 4130,4456 4152,4456 4156,4460 4214,4460 4232,4478 4300,4478 v1(4340,4518) ; v1(5148,3902) v1@5152,3902 ; R9.2@5157.04,3870 v1@5157,3905
  Inner2 w10: v1(5148,3902) 5154,3908 5284,3908 5284,4016 v1(5308,4040)
  Bottom Layer w5: 3359.5,4093.3 3381.8,4093.3 ; 3384,4094 3386,4096 3404,4096 3406,4094 3428,4094 v1(3428,4058)
  Bottom Layer w10: 3231.8,4053.9 v1@3253.9,4053.9 ; v1(3248,4048) v1@3253.9,4053.9 ; v1(3274,4048) v1@3274,4050 ; J2.A7@3314,4093.3 J2.A7@3314.51,4093.3 3350,4093.3 ; J2.B7@3321.8,4053.9 v1@3253.9,4053.9 ; 3350,4094 3350,4093.3 ; 3359.5,4093.3 3350,4093.3 ; v1(4340,4518) 4350,4508 4408,4508 4444,4544 4640,4544 4686,4590 4746,4590 4760,4604 4790,4604 4818,4632 5150,4632 5264,4518 5264,4418 5298,4384 5298,4050 v1(5308,4040) ; v1@3253.9,4053.9 3254,4054 3314.51,4054 3350,4054 3350,4093.3
USB_DM_MCU: R9.1 U2.13 | length 110
  Top Layer w10: R9.1@5122.96,3870 5122.96,3895.86 5094.02,3924.81 U2.13@5068.2,3924.81 ; U2.13@5068.2,3924.81 U2.13@5059.49,3924.8 U2.13@5068.2,3924.81
USB_DP: D2.1 J2.A6 J2.B6 R10.2 | length 3664.6
  Top Layer w10: v1(3618,4088) v1(3638,4108) 3638,4346 3702,4410 3794,4318 3834,4358 3964,4358 4016,4410 4074,4410 4084,4420 4116,4420 4136,4440 4158,4440 4162,4444 4220,4444 4238,4462 4310,4462 4334,4486 4526,4486 4584,4544 4614,4544 4634,4564 4660,4564 4686,4590 4810,4590 v1(4826,4606) ; 3701.2,4410 D2.1@3701.22,4500 ; 5162,3965 R10.2@5162.04,4025 ; 5166,3962 5226,3962 5254,3990 v1(5316,3990)
  Bottom Layer w10: 3231.8,4073.6 J2.A6@3321.8,4073.6 ; 3254,4078 3288,4112 ; 3288,4113 3321.79,4113 3450,4113 ; 3410,4108 3454,4108 ; 3450,4112 3454,4108 ; v1(3618,4088) 3474,4088 3454,4108 ; v1(3638,4108) 3454,4108 ; v1(4826,4606) 4830,4602 5154,4602 5248,4508 5248,4412 5282,4378 5282,4024 v1(5316,3990)
USB_DP_MCU: R10.1 U2.14 | length 514.1
  Top Layer w10: v1(4975.1,3850.34) 4975.1,3858.99 5018.45,3902.34 5018.45,3970.23 5023.03,3974.81 U2.14@5059.49,3974.8 ; R10.1@5127.96,4025 5133.44,4030.48 v1(5133.44,4070.41)
  Inner2 w10: v1(4975.1,3850.34) 4975.1,3876.7 5133.44,4035.04 v1(5133.44,4070.41)
VBAT: C1.1 J1.1 R28.1 U1.2 U1.3 U5.2 U5.3 | length 4077.2
  Top Layer w9.88: v2(3329.4,3784.67) v2@3329.4,3790.23 ; U5.2@3650.16,3758.09 U5.3@3669.84,3758.09 3669.84,3738.28 3675.57,3738.28 v2(3682.3,3731.55) ; R28.1@5150,3187.96 5150,3156.84 v2(5151.51,3155.33)
  Top Layer w10: C1.1@3235.43,3848.03 3293.23,3790.23 3329.4,3790.23 3428.09,3790.23 3432.71,3794.85 ; U1.3@3460.95,3775.16 3432.71,3775.17 3432.71,3794.85 ; U1.2@3460.95,3794.84 3432.71,3794.85
  Inner1 w9.88: v2(3329.4,3784.67) 3402.57,3784.66 3414.84,3772.39 3641.46,3772.39 v2(3682.3,3731.55) 3802.77,3611.08 4305.73,3611.08 4400.2,3516.61 4580.13,3516.61 4748.84,3347.9 5104.38,3347.9 5124.81,3368.33 5166.9,3368.33 5185.09,3350.14 5185.09,3188.91 v2(5151.51,3155.33)
  Inner2 w9.88: v2(5151.51,3155.33) 5186.29,3120.55 5497.88,3120.55 5525.02,3147.69 J1.1@6548.8,3147.69
VBAT_MODEM: C32.1 C33.1 C34.1 C35.1 R28.2 U3.42 U3.43 | length 3534.7
  Top Layer w15: v1(5126,3214) R28.2@5150,3222.04
  Top Layer w16: C33.1@5305,3199.37 5380,3199.4 ; C35.1@5380,3161.54 5380,3199.4 ; 5380,3251.5 5380,3199.4 ; 5395,3199.4 5380,3199.4 ; v1@5402,3196 v1(5412,3196) ; 5450,3564.4 C34.1@5510,3564.37 ; C34.1@5504,3572 5516,3584 5822,3584 5846,3560 v1(5932,3560)
  Bottom Layer w16: v1(5126,3214) 5158,3182 5250,3182 5268,3200 ; 5268,3196 v1(5412,3196) 5722,3196 ; 5365.1,3057.2 U3.43@5365.08,3147.16 ; 5372,3072 5408.4,3072 ; v1(5388,3188) 5730,3188 ; 5408.4,3057.2 5408.4,3072 ; U3.42@5408.39,3147.16 5408.4,3072 ; 5718,3200 5722,3196 ; v1(5932,3560) C32.1@6043.4,3448.6 ; C32.1@6043.31,3448.62 C32.1@6043.4,3448.6 ; 6133.3,3448.6 C32.1@6043.4,3448.6 ; 5408.4,3072 5696,3072 5774,3150 ; 5722,3196 5730,3188 ; 5730,3188 5736,3182 5812,3182 ; 5774,3150 5890,3150 5890,3152 ; 5774,3150 5776,3152 5890,3152 ; 5812,3182 5890,3260 ; 5812,3182 5824,3182 ; 5824,3182 5890,3248 ; 5824,3182 5848,3182 5890,3224 ; 5890,3152 5890,3224 ; 5890,3224 5890,3248 ; 5890,3248 5890,3260 ; 5890,3260 5890,3294 6044,3448 C32.1@6043.4,3448.6
VBUS_PROT: C2.1 C3.1 D8.1 F1.2 U1.13 | length 1031.4
  Top Layer w6: C2.1@3610,3893.46 3598.9,3893.5 v1(3570.71,3865.31) ; v1(3570.71,3865.31) 3570.71,3844.1 U1.13@3549.53,3844.05 v1(3570.71,3865.31)
  Top Layer w10: C3.1@3475,3980.63 3475,3959.39 v1(3496.21,3959.39) ; C3.1@3475,3980.63 3621.89,4127.52 3621.89,4467.52 3631.89,4477.52 F1.2@3631.89,4524 ; C2.1@3610,3893.46 3669.1,3893.5 D8.1@3690,3872.6
  Bottom Layer w10: v1(3496.21,3959.39) 3496.21,3865.31 v1(3570.71,3865.31)
VBUS_RAW: F1.1 J2.A4B9 J2.B4A9 | length 1385.9
  Top Layer w10: v1(3558.11,4454) 3518.11,4494 F1.1@3518.11,4524 3565.77,4524
  Top Layer w16: v1(3372,3994) 3372,4084 3414,4126 ; 3412,4126 v1(3412,4188) 3412,4508 ; 3412,4510 3412,4508 ; 3428,4524 3412,4508 ; 3428.1,4524 F1.1@3518.11,4524
  Bottom Layer w10: v1(3558.11,4454) 3568.11,4444 3608.11,4444 3628.11,4464 ; 3608.15,4533.3 3618.11,4523.34 3618.11,4494 3628.11,4484 3628.11,4464 ; 3801.85,4533.3 3801.85,4507.74 3782.12,4488.02 3782.12,4448.02 3768.11,4434 3658.11,4434 3628.11,4464
  Bottom Layer w16: J2.A4B9@3321.8,3986.6 3411.8,3986.6 ; J2.B4A9@3321.8,4180.3 v1@3411.8,4180.3
VSYS_RAW: C4.1 C5.1 C19.1 U1.5 U1.10 U1.11 U4.1 U4.10 | length 4083.9
  Top Layer w10: 3660,3454.9 U4.1@3733.1,3454.9 ; v1(3716,3472) U4.1@3733.1,3454.9 ; U4.1@3734,3454 U4.1@3733.1,3454.9 ; U4.1@3735.02,3454.87 U4.1@3733.1,3454.9 ; U4.10@3799.98,3454.87 3800,3544 ; 3800,3544.9 3800,3544 ; v1(3832,3576) 3800,3544 ; v1(3938,3836) 3946,3836 v1@3948,3836
  Top Layer w12: U1.10@3579.05,3775.16 3607.1,3775.2 ; U1.10@3580,3780 U1.11@3580,3794 ; v1(3606,3732) 3610,3736 3610,3774 3608,3776 ; v1(3946,3808) 3946,3810 3946,3814 3946,3836 v1@3946,3838
  Top Layer w15: U1.5@3490,3726 3490,3702 3506,3686 v1(3520,3686) ; v1@3958,3844 v1(3962,3844)
  Top Layer w20: 3380,3676.5 C5.1@3470,3676.54 ; v1(3438,3658) 3456,3676 C5.1@3470,3676 ; C4.1@3545.63,3615 v1@3545.6,3660 ; v1(3942,3782) 3958,3798 3946,3810 3944,3812 3946,3814 3958,3826 ; 3950.6,3840 C19.1@3950.63,3930 ; v1@3955,3835 v1(3970,3820)
  Inner2 w10: v1(3716,3472) 3921,3677 3934,3690 v1(3938,3690)
  Inner2 w12: v1(3606,3732) 3642,3768 3906,3768 v1(3946,3808)
  Inner2 w15: v1(3772,3570) 3890,3688 3910,3688 3921,3677 v1(3936,3662)
  Inner2 w20: v1(3438,3658) 3628,3468 3644,3468 ; v1(3546,3654) 3546,3566 3644,3468 ; v1(3986,3664) 3946,3624 ; v1(3986,3690) 3946,3650 3946,3624 ; 3644,3468 3650,3468 3652,3466 ; 3644,3468 3646,3466 3652,3466 ; 3652,3466 3946,3466 3946,3624
  Bottom Layer w10: v1(3832,3576) 3792,3616 3792,3816 3850,3874 3936,3874 v1(3946,3864) ; v1(3938,3690) v1(3938,3836)
  Bottom Layer w15: v1(3520,3686) 3528,3694 3562,3694 3588,3668 3662,3668 3760,3570 v1(3772,3570) ; v1(3936,3662) 3954,3680 3954,3696 3954,3722 3954,3726 3950,3730 ; 3944,3736 3946,3734 ; 3944,3794 3944,3826 v1(3962,3844)
  Bottom Layer w18: 3946,3734 3950,3730
  Bottom Layer w20: 3942,3730 3942,3734 ; 3944,3736 3942,3734 ; 3946,3726 3946,3704 3954,3696 v1(3986,3664) ; v1(3970,3820) 3944,3794 3942,3792 3942,3734 ; v1(3986,3690) 3954,3722 3942,3734
pads on no net: J2.A8 J2.B8 J4.C6 J5.4 J5.7 LED1.1 U1.9 U1.15 U2.16 U2.26 U2.28 U2.29 U2.30 U3.2 U3.3 U3.4 U3.5 U3.6 U3.8 U3.9 U3.16 U3.20 U3.21 U3.22 U3.23 U3.26 U3.28 U3.29 U3.30 U3.31 U3.32 U3.33 U3.38 U3.39 U3.44 U3.49 U3.50 U3.51 U3.52 U3.53 U3.54 U3.55 U3.56 U3.57 U3.58 U3.59 U3.60 U3.61 U3.62 U3.63 U3.64 U3.65 U3.66 U3.67 U3.68 U3.69 U3.74 U3.75 U3.76 U3.77 U3.78 U3.79 U3.80 U3.81 U3.82 U3.83 U3.84 U3.85 U3.86 U3.87 U3.96 U3.97 U3.98 U3.99 U3.101 U3.102 U3.103 U3.104 U3.105 U3.106 U3.107 U3.108 U3.109 U4.5 U5.5 U5.6 U6.4 U9.9

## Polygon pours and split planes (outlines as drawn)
GND on Top Layer (solid, remove dead copper, pour order 0): 3020,3020 3020,5145.4 6917,5145.4 6917,3020
GND on Bottom Layer (solid, remove dead copper, pour order 2): 3020,3020 3020,5145.4 6917,5145.4 6917,3020
GND on Inner1 (solid, remove dead copper): 3020,3020 3020,5145.4 6917,5145.4 6917,3020
+3V3 on Inner2 (solid, remove dead copper): 3020,3020 3020,5145.4 6917,5145.4 6917,3020

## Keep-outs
Board Outline Layer:
  region: 4320.98,3019.53 4320.98,3299.8 5109.02,3299.8 5109.02,3019.53
  region: 4835.36,4324.86 4835.36,4635.14 5164.64,4635.14 5164.64,4324.86
  lines w10: 3000,3080 3001.54,3064.39 3006.09,3049.39 3013.48,3035.55 3023.43,3023.43 3035.55,3013.48 3049.39,3006.09 3064.39,3001.54 3080,3000 6857,3000 6872.61,3001.54 6887.61,3006.09 6901.45,3013.48 6913.57,3023.43 6923.52,3035.55 6930.91,3049.39 6935.46,3064.39 6937,3080 6937,5085.4 6935.46,5101.01 6930.91,5116.01 6923.52,5129.85 6913.57,5141.97 6901.45,5151.92 6887.61,5159.31 6872.61,5163.86 6857,5165.4 3080,5165.4 3064.39,5163.86 3049.39,5159.31 3035.55,5151.92 3023.43,5141.97 3013.48,5129.85 3006.09,5116.01 3001.54,5101.01 3000,5085.4 3000,3080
